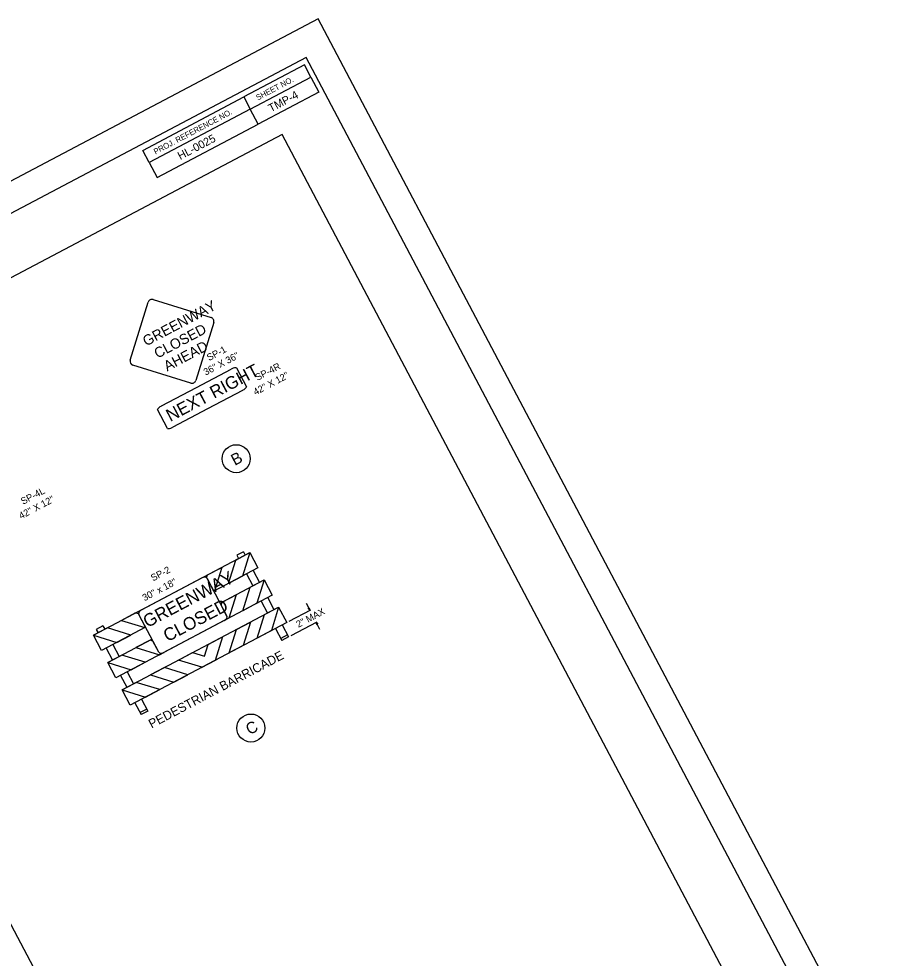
# Model space of a CAD drawing. Extents: x 1485914 to 1489436, y 493744 to 499689.
# Drawn here: x 1488661 to 1489436, y 498867 to 499689 of the extents above; entities that cross this region are included whole.
import ezdxf

# ---------------------------------------------------------------- set-up
doc = ezdxf.new("R2010")
doc.units = 0
for name, color, linetype in [('Default', 7, 'Continuous'), ('DEV BORDER CELL', 7, 'Continuous'), ('DEV TYPE 3 BARRICADE SINGLE WITH R11-2 CELL', 7, 'Continuous'), ('Gray Area Fill Shapes', 7, 'Continuous'), ('Scratch_Level_0', 7, 'Continuous'), ('Sheet Plot Border Outside CELL', 7, 'Continuous'), ('WS SP-200 CELL', 7, 'Continuous'), ('WS SP-4L CELL', 7, 'Continuous'), ('WS SP-4R CELL', 7, 'Continuous'), ('WZ OSDR CELL', 7, 'Continuous')]:
    doc.layers.add(name, color=color, linetype=linetype)

msp = doc.modelspace()

# ---------------------------------------------------------------- linework, layer by layer
at = {"layer": 'Default'}
for p, q in [((1488897.18, 499161.63), (1488916.09, 499171.61)), ((1488911.94, 499177.34), (1488915.21, 499171.15)), ((1488913.83, 499172.68), (1488914.71, 499173.15)), ((1488898.74, 499149.08), (1488921.61, 499161.16)), ((1488924, 499154.5), (1488920.73, 499160.69)), ((1488921.22, 499158.69), (1488922.1, 499159.16))]:
    msp.add_line(p, q, dxfattribs=at)
for points in [[(1488914.71, 499173.15), (1488913.83, 499172.68), (1488915.21, 499171.15)], [(1488921.22, 499158.69), (1488922.1, 499159.16), (1488920.73, 499160.69)]]:
    msp.add_lwpolyline(points, close=True, dxfattribs=at)
for points in [[(1488914.71, 499173.15), (1488915.21, 499171.15), (1488913.83, 499172.68)], [(1488921.22, 499158.69), (1488920.73, 499160.69), (1488922.1, 499159.16)]]:
    msp.add_lwpolyline(points, dxfattribs=at)
at = {"layer": 'DEV BORDER CELL'}
msp.add_line((1488863.07, 499609.57), (1488916.12, 499637.58), dxfattribs=at)
for points in [[(1488911.97, 499654.77), (1487585.52, 498954.38), (1488075.8, 498025.87), (1489402.24, 498726.26)], [(1488863.07, 499609.57), (1488916.12, 499637.58), (1488910.52, 499648.2), (1488857.46, 499620.18)], [(1488863.07, 499609.57), (1488916.12, 499637.58), (1488923.13, 499624.32), (1488870.07, 499596.31)], [(1488769.03, 499573.49), (1488857.46, 499620.18), (1488863.07, 499609.57), (1488774.64, 499562.88)], [(1488863.07, 499609.57), (1488774.64, 499562.88), (1488781.64, 499549.61), (1488870.07, 499596.31)]]:
    msp.add_lwpolyline(points, close=True, dxfattribs=at)
at = {"layer": 'DEV TYPE 3 BARRICADE SINGLE WITH R11-2 CELL'}
for p, q in [((1488725.84, 499149.37), (1488862.67, 499221.62)), ((1488850.36, 499215.12), (1488862.67, 499221.62)), ((1488857.08, 499222.38), (1488851.27, 499219.31)), ((1488862.67, 499221.62), (1488856.34, 499201.12)), ((1488857.08, 499222.38), (1488858.61, 499219.48)), ((1488862.67, 499221.62), (1488869.76, 499208.21)), ((1488844.03, 499194.62), (1488850.36, 499215.12)), ((1488851.27, 499219.31), (1488852.8, 499216.41)), ((1488825.73, 499202.12), (1488838.05, 499208.62)), ((1488869.76, 499208.21), (1488831.17, 499187.83)), ((1488838.05, 499208.62), (1488831.72, 499188.12)), ((1488865.69, 499206.06), (1488871.21, 499195.61)), ((1488824.92, 499199.48), (1488825.73, 499202.12)), ((1488831.17, 499187.83), (1488825.23, 499199.07)), ((1488836.69, 499177.38), (1488875.28, 499197.75)), ((1488856.34, 499201.12), (1488844.03, 499194.62)), ((1488859.88, 499202.99), (1488865.4, 499192.54)), ((1488862.97, 499191.25), (1488875.28, 499197.75)), ((1488875.28, 499197.75), (1488868.95, 499177.25)), ((1488875.28, 499197.75), (1488882.36, 499184.34)), ((1488831.72, 499188.12), (1488831.17, 499187.83)), ((1488856.63, 499170.75), (1488862.97, 499191.25)), ((1488882.36, 499184.34), (1488745.53, 499112.08)), ((1488838.34, 499178.25), (1488850.65, 499184.75)), ((1488850.65, 499184.75), (1488844.32, 499164.25)), ((1488872.49, 499179.12), (1488878.01, 499168.67)), ((1488878.3, 499182.19), (1488883.82, 499171.74)), ((1488751.05, 499101.63), (1488887.88, 499173.88)), ((1488837.56, 499175.73), (1488838.34, 499178.25)), ((1488842.62, 499166.14), (1488837.56, 499175.73)), ((1488868.95, 499177.25), (1488856.63, 499170.75)), ((1488875.57, 499167.38), (1488887.88, 499173.88)), ((1488887.88, 499173.88), (1488881.55, 499153.38)), ((1488887.88, 499173.88), (1488894.97, 499160.47)), ((1488762.78, 499168.88), (1488750.46, 499162.37)), ((1488750.46, 499162.37), (1488770.96, 499156.04)), ((1488765.41, 499168.06), (1488762.78, 499168.88)), ((1488771.51, 499156.33), (1488765.57, 499167.57)), ((1488844.32, 499164.25), (1488840.32, 499162.14)), ((1488869.24, 499146.88), (1488875.57, 499167.38)), ((1488738.15, 499155.87), (1488725.84, 499149.37)), ((1488734.18, 499157.49), (1488728.37, 499154.42)), ((1488728.37, 499154.42), (1488729.9, 499151.52)), ((1488771.51, 499156.33), (1488732.92, 499135.95)), ((1488734.18, 499157.49), (1488735.71, 499154.58)), ((1488758.65, 499149.54), (1488738.15, 499155.87)), ((1488894.97, 499160.47), (1488758.13, 499088.21)), ((1488770.96, 499156.04), (1488771.51, 499156.33)), ((1488840.29, 499162.12), (1488787.59, 499134.3)), ((1488844.61, 499133.88), (1488850.94, 499154.38)), ((1488850.94, 499154.38), (1488863.26, 499160.88)), ((1488863.26, 499160.88), (1488856.92, 499140.38)), ((1488885.09, 499155.25), (1488890.61, 499144.8)), ((1488890.9, 499158.32), (1488896.42, 499147.86)), ((1488732.92, 499135.95), (1488725.84, 499149.37)), ((1488725.84, 499149.37), (1488746.34, 499143.04)), ((1488738.44, 499125.5), (1488777.03, 499145.88)), ((1488746.34, 499143.04), (1488758.65, 499149.54)), ((1488826.32, 499141.37), (1488838.63, 499147.88)), ((1488838.63, 499147.88), (1488832.3, 499127.38)), ((1488881.55, 499153.38), (1488869.24, 499146.88)), ((1488895.5, 499149.61), (1488889.69, 499146.54)), ((1488896.42, 499147.86), (1488890.61, 499144.8)), ((1488736.99, 499138.1), (1488742.51, 499127.65)), ((1488742.79, 499141.17), (1488748.31, 499130.71)), ((1488775.38, 499145), (1488763.07, 499138.5)), ((1488763.07, 499138.5), (1488783.57, 499132.17)), ((1488777.9, 499144.23), (1488775.38, 499145)), ((1488782.97, 499134.63), (1488777.9, 499144.23)), ((1488823.08, 499130.9), (1488826.32, 499141.37)), ((1488856.92, 499140.38), (1488844.61, 499133.88)), ((1488750.75, 499132), (1488738.44, 499125.5)), ((1488771.25, 499125.67), (1488750.75, 499132)), ((1488783.57, 499132.17), (1488787.57, 499134.28)), ((1488800.3, 499127.64), (1488812.61, 499134.14)), ((1488812.61, 499134.14), (1488823.08, 499130.9)), ((1488745.53, 499112.08), (1488738.44, 499125.5)), ((1488738.44, 499125.5), (1488758.94, 499119.17)), ((1488758.94, 499119.17), (1488771.25, 499125.67)), ((1488820.8, 499121.3), (1488800.3, 499127.64)), ((1488832.3, 499127.38), (1488819.99, 499120.87)), ((1488820.8, 499121.3), (1488833.11, 499127.8)), ((1488749.59, 499114.23), (1488755.11, 499103.78)), ((1488755.4, 499117.3), (1488760.92, 499106.84)), ((1488787.98, 499121.13), (1488775.67, 499114.63)), ((1488775.67, 499114.63), (1488796.17, 499108.3)), ((1488808.49, 499114.8), (1488787.98, 499121.13)), ((1488796.17, 499108.3), (1488808.49, 499114.8)), ((1488763.36, 499108.13), (1488751.05, 499101.63)), ((1488783.86, 499101.8), (1488763.36, 499108.13)), ((1488758.13, 499088.21), (1488751.05, 499101.63)), ((1488751.05, 499101.63), (1488771.55, 499095.3)), ((1488771.55, 499095.3), (1488783.86, 499101.8)), ((1488762.2, 499090.36), (1488767.72, 499079.9)), ((1488768, 499093.43), (1488773.52, 499082.97)), ((1488772.6, 499084.71), (1488766.8, 499081.65)), ((1488773.52, 499082.97), (1488767.72, 499079.9))]:
    msp.add_line(p, q, dxfattribs=at)
for points in [[(1488767.91, 499171.58), (1488820.6, 499199.41)], [(1488825.23, 499199.07), (1488842.62, 499166.14)], [(1488782.96, 499134.63), (1488765.57, 499167.57)]]:
    msp.add_lwpolyline(points, dxfattribs=at)
for centre, major_axis, start_param, end_param in [((1488821.75, 499197.24), (3.48, 1.84), 0, 1.570796), ((1488821.75, 499197.24), (3.48, 1.84), 6.283185, 6.491582), ((1488769.05, 499169.41), (-3.48, -1.84), 4.712162, 6.283185), ((1488769.05, 499169.41), (-3.48, -1.84), 6.074789, 6.283185), ((1488839.14, 499164.3), (-3.48, -1.84), 1.570796, 3.141593), ((1488839.15, 499164.3), (3.48, 1.84), 4.712389, 6.283185), ((1488786.44, 499136.47), (-3.48, -1.84), 0, 1.571024), ((1488786.45, 499136.47), (3.48, 1.84), 3.141593, 4.712389)]:
    msp.add_ellipse(centre, major_axis=major_axis, ratio=0.625, start_param=start_param, end_param=end_param, dxfattribs=at)
at = {"layer": 'Gray Area Fill Shapes'}
for centre in [(1488850.76, 499303.76), (1488863.61, 499068.16)]:
    msp.add_circle(centre, 12.25, dxfattribs=at)
at = {"layer": 'Scratch_Level_0'}
msp.add_lwpolyline([(1488891.1, 499587.21), (1487653.08, 498933.51), (1488096.67, 498093.43), (1488873.83, 498503.79), (1488818.61, 498608.38), (1489279.46, 498851.72)], close=True, dxfattribs=at)
at = {"layer": 'Sheet Plot Border Outside CELL'}
msp.add_lwpolyline([(1487943.33, 497927.66), (1489436.02, 498715.83), (1488922.4, 499688.55), (1487429.71, 498900.38)], close=True, dxfattribs=at)
at = {"layer": 'WS SP-200 CELL'}
msp.add_line((1488831.06, 499422.92), (1488815.42, 499372.28), dxfattribs=at)
for points in [[(1488778.11, 499442.94), (1488828.75, 499427.3)], [(1488758.09, 499389.99), (1488773.73, 499440.63)], [(1488811.04, 499369.97), (1488760.4, 499385.61)]]:
    msp.add_lwpolyline(points, dxfattribs=at)
for centre, start, end in [((1488777.08, 499439.6), 117.82858, 162.83509), ((1488777.08, 499439.6), 72.82206, 117.82858), ((1488827.72, 499423.95), 342.83509, 72.83509), ((1488761.44, 499388.96), 162.83509, 252.83509), ((1488812.08, 499373.32), 252.83509, 297.83509), ((1488812.08, 499373.32), 297.83509, 342.83509)]:
    msp.add_arc(centre, 3.5, start, end, dxfattribs=at)
at = {"layer": 'WS SP-4R CELL'}
for p, q in [((1488815.94, 499366), (1488846.4, 499382.09)), ((1488785.48, 499349.91), (1488815.94, 499366))]:
    msp.add_line(p, q, dxfattribs=at)
for points in [[(1488851, 499383.13), (1488859.66, 499366.72)], [(1488856.21, 499363.52), (1488825.74, 499347.43)], [(1488790.69, 499330.3), (1488782.02, 499346.71)], [(1488825.74, 499347.43), (1488795.28, 499331.34)]]:
    msp.add_lwpolyline(points, dxfattribs=at)
for centre, major_axis, start_param, end_param in [((1488846.98, 499381), (4.02, 2.12), 0, 1.570796), ((1488855.64, 499364.6), (-4.02, -2.12), 1.570796, 3.141593), ((1488786.05, 499348.83), (-4.02, -2.12), 4.712162, 6.283185), ((1488794.71, 499332.43), (-4.02, -2.12), 0, 1.570796)]:
    msp.add_ellipse(centre, major_axis=major_axis, ratio=0.269231, start_param=start_param, end_param=end_param, dxfattribs=at)
at = {"layer": 'WZ OSDR CELL'}
msp.add_lwpolyline([(1487648.11, 498943.96), (1488414.63, 499348.7), (1488845.5, 498532.69), (1488078.98, 498127.95)], close=True, dxfattribs=at)
for centre in [(1488850.76, 499303.76), (1488863.61, 499068.16)]:
    msp.add_circle(centre, 12.25, dxfattribs=at)

# ---------------------------------------------------------------- texts
at = {"layer": 'Default'}
msp.add_text('2" MAX', height=6, rotation=27.83509, dxfattribs=at).set_placement((1488905.17, 499155.77))
at = {"layer": 'DEV BORDER CELL'}
for s, height, rotation, p in [('SHEET NO.', 4.999, 27.83565, (1488869.69, 499617.02)), ('TMP-4', 7, 27.83509, (1488881.12, 499606.66)), ('PROJ. REFERENCE NO.', 4.9992, 27.83565, (1488780.17, 499569.76)), ('HL-0025', 7, 27.83509, (1488801.81, 499564.95))]:
    msp.add_text(s, height=height, rotation=rotation, dxfattribs=at).set_placement(p)
at = {"layer": 'DEV TYPE 3 BARRICADE SINGLE WITH R11-2 CELL'}
for s, height, p in [('GREENWAY', 11.132, (1488773.04, 499155.6)), ('SP-2', 6, (1488777.98, 499196.35)), ("30'' x 18''", 6, (1488770.57, 499178.99)), ('CLOSED', 11.132, (1488790.72, 499143.23)), ('PEDESTRIAN BARRICADE', 7.8816, (1488776.7, 499067.71))]:
    msp.add_text(s, height=height, rotation=27.83509, dxfattribs=at).set_placement(p)
at = {"layer": 'WS SP-200 CELL'}
for s, height, p in [('GREENWAY', 9, (1488771.98, 499401.93)), ('CLOSED', 9, (1488781.92, 499391.18)), ('AHEAD', 9, (1488790.36, 499379.97)), ('SP-1', 6, (1488827, 499389.1)), ("36'' X 36''", 6, (1488824.1, 499376.38))]:
    msp.add_text(s, height=height, rotation=27.83509, dxfattribs=at).set_placement(p)
at = {"layer": 'WS SP-4L CELL'}
for s, p in [('SP-4L', (1488664.3, 499263.39)), ("42'' X 12''", (1488662.61, 499250.7))]:
    msp.add_text(s, height=6, rotation=27.83509, dxfattribs=at).set_placement(p)
at = {"layer": 'WS SP-4R CELL'}
for s, height, p in [('NEXT RIGHT', 11, (1488793.07, 499335.83)), ('SP-4R', 6, (1488869.34, 499371.72)), ("42'' X 12''", 6, (1488867.65, 499359.03))]:
    msp.add_text(s, height=height, rotation=27.83509, dxfattribs=at).set_placement(p)
at = {"layer": 'WZ OSDR CELL'}
for s, p in [('B', (1488849.51, 499297.44)), ('C', (1488862.41, 499061.87))]:
    msp.add_text(s, height=10, rotation=27.83509, dxfattribs=at).set_placement(p)

doc.saveas('drawing.dxf')
